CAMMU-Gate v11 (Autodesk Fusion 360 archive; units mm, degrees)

design "CAMMU-Gate" references "MR63ZZ"
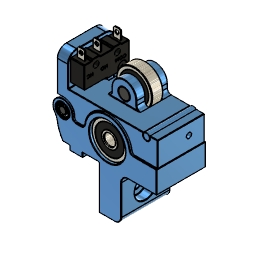
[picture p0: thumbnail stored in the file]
description: Part Number
part number: CAMMU-Linear-Rail-Lead-Screw
part number: Endstop Limit Switch v1
part number: Screw
part number: Brass body
part number: Brass NUT
part number: 625Z_1
named bodies: "Gate bottom (NEW)", "Gate top (NEW)"

design "MR63ZZ"
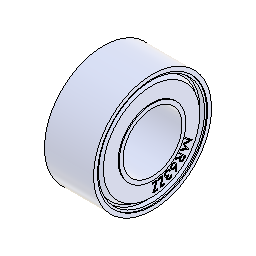
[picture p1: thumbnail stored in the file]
description: STEP AP214
part number: MR63ZZ
description: Part Number
part number: outer shell - mz63zz
part number: inner shell - mz63zz
part number: 1mm ball bearing sphere
part number: MR63ZZ - seal
base_feature "Base Feature1"
base_feature "Base Feature1"
base_feature "Base Feature1"
base_feature "Base Feature1"
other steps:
create_component "CreateComponent1"
create_component "CreateComponent2"
create_component "CreateComponent3"
create_component "CreateComponent4"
